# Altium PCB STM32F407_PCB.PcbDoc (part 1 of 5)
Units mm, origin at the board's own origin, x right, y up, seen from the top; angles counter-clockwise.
Board outline 100.27 x 100.27 mm, 2 copper layers (Top Layer, Bottom Layer); 134 components, 132 nets, 659 pads, 288 vias.
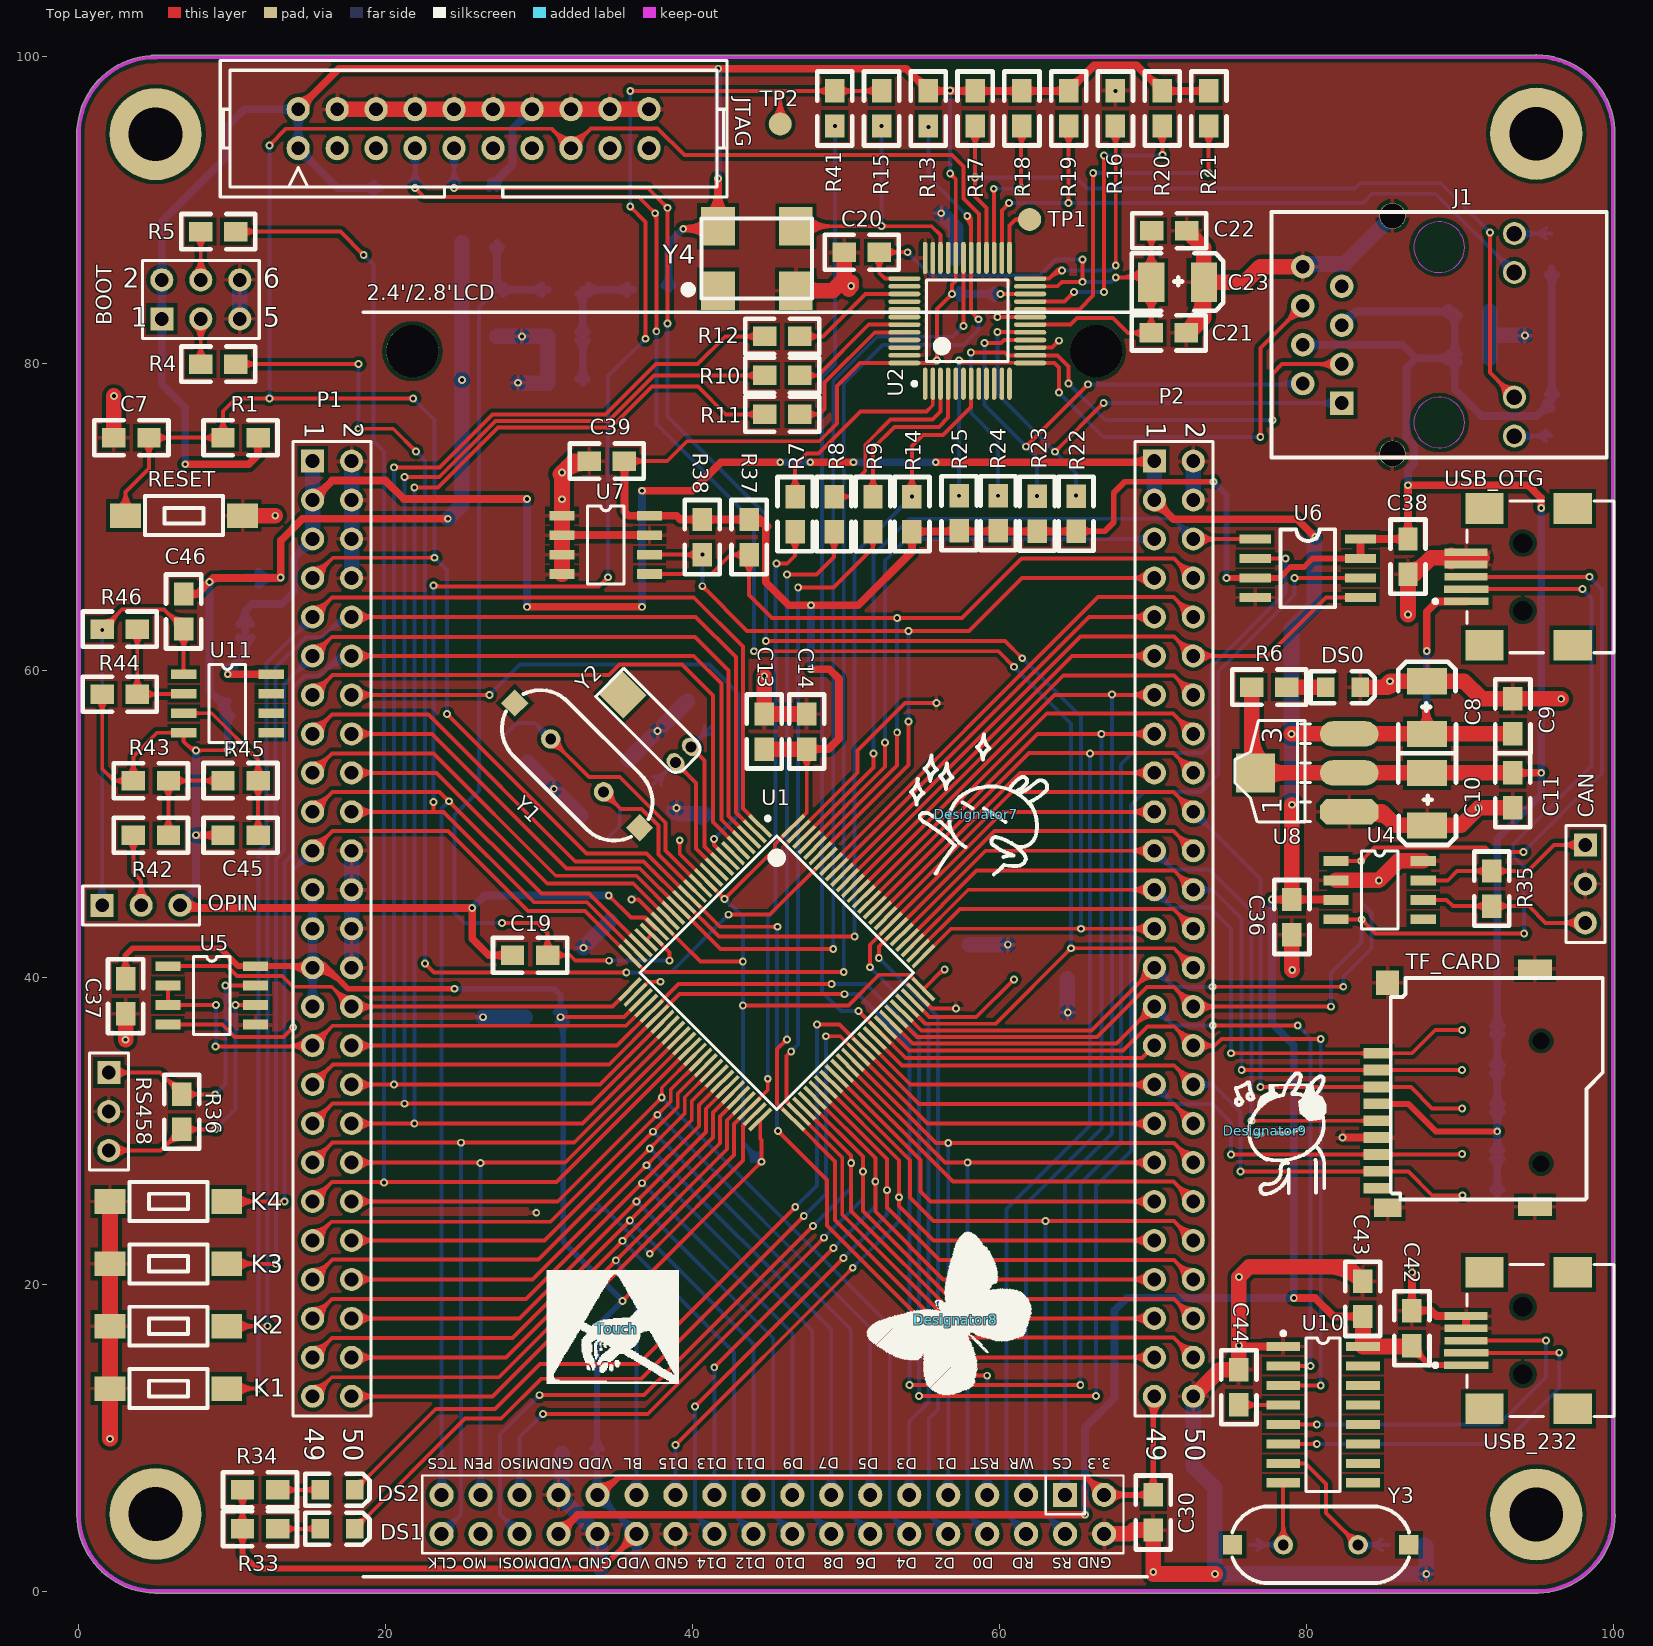
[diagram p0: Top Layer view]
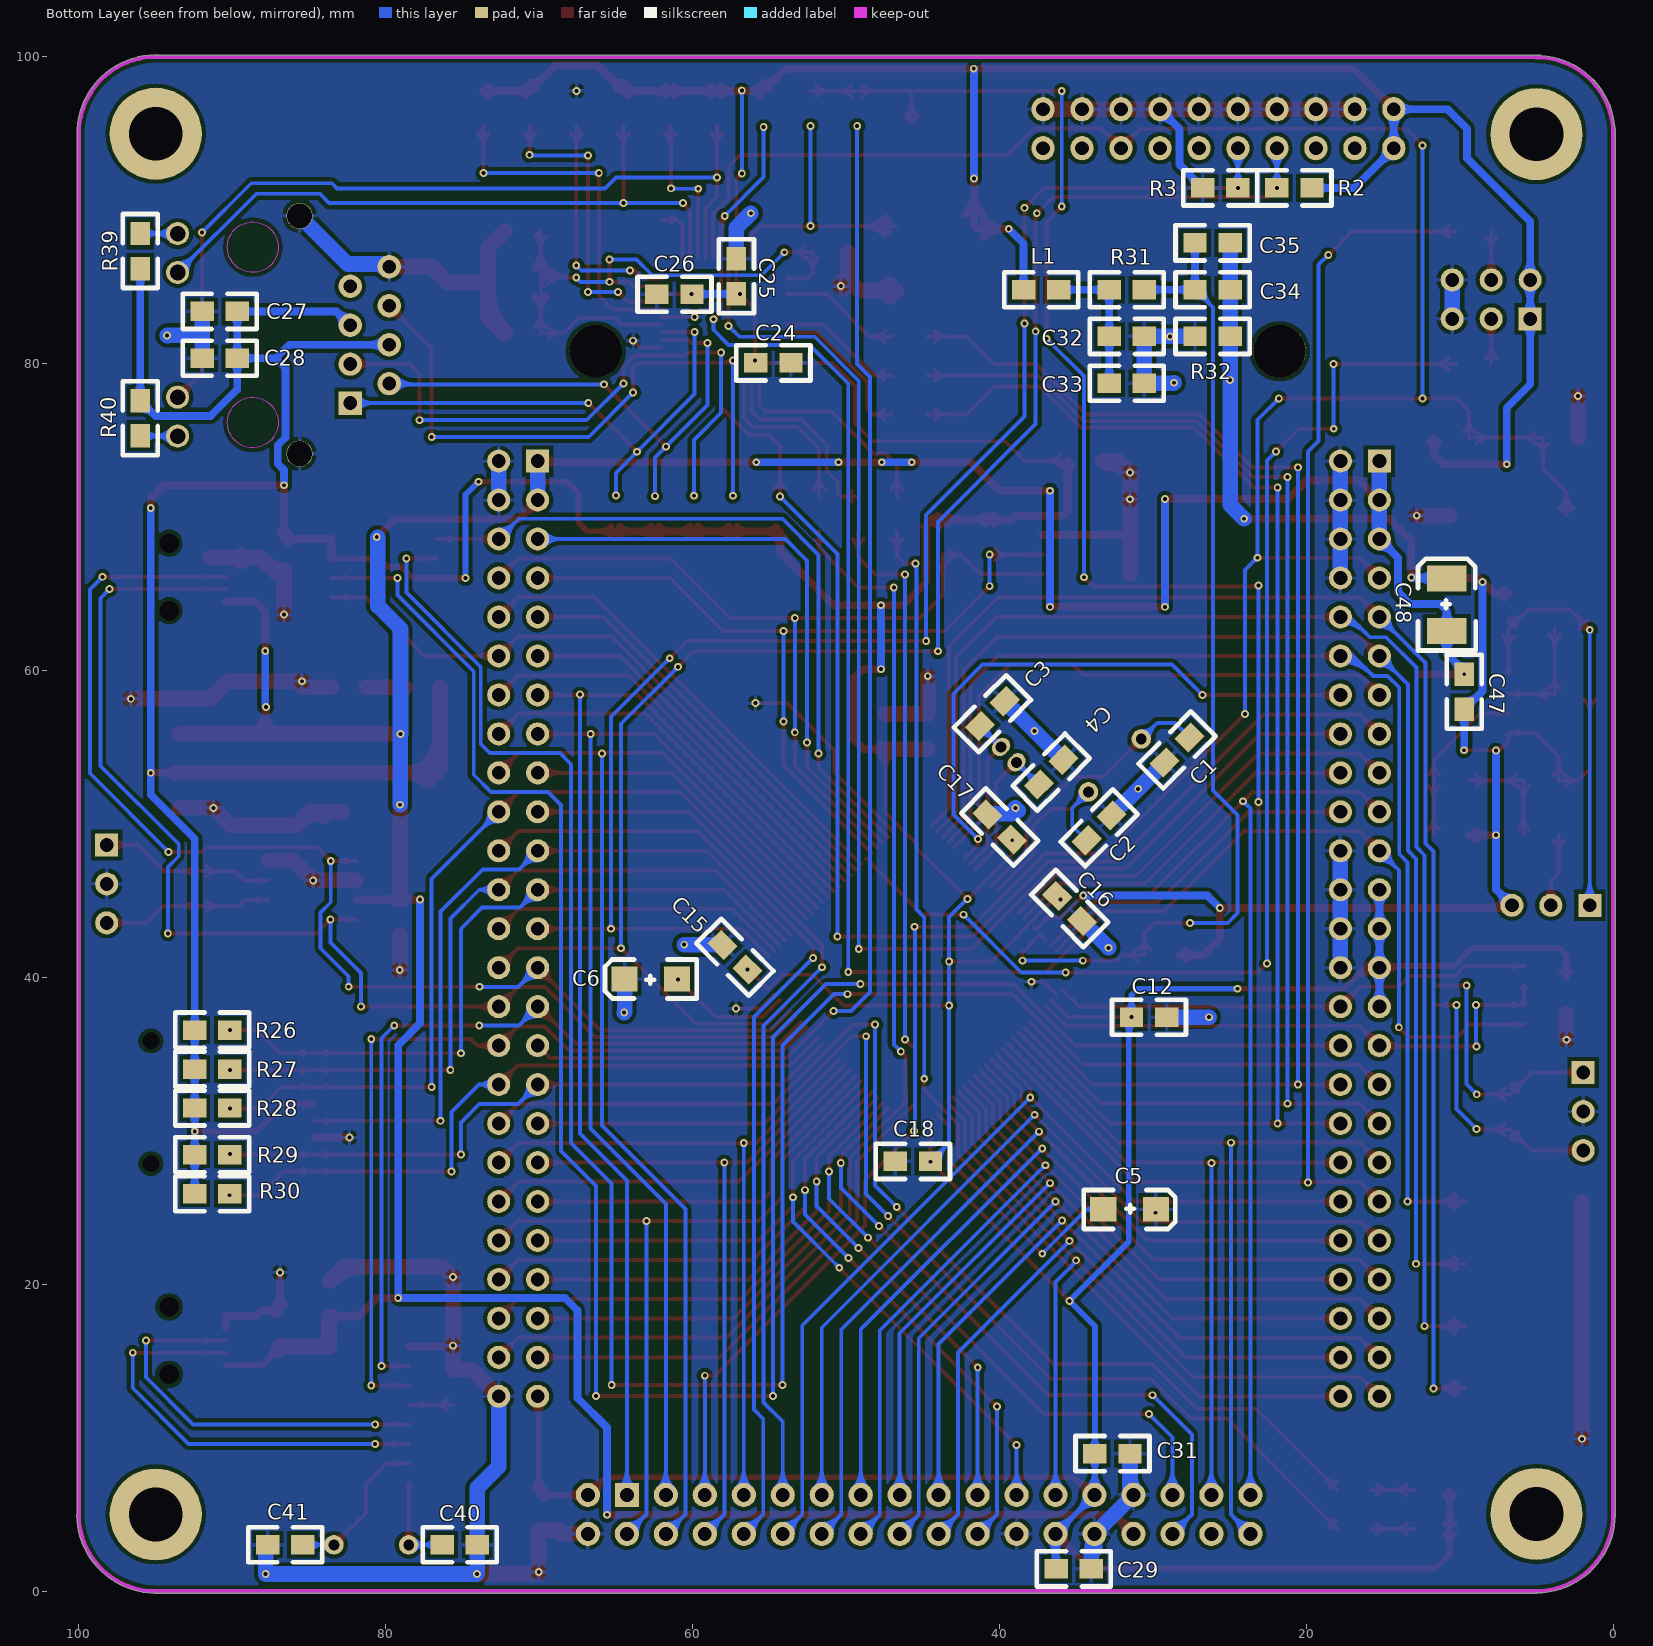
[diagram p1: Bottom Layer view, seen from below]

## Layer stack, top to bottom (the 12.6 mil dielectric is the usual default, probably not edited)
Top Layer: signal copper 0.0356
Dielectric: dielectric 0.32, FR-4, Dk 4.8
Bottom Layer: signal copper 0.0356

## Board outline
-0.127,4.992 cw(c0,4.994) -0.127,4.994 -0.127,4.996 cw(c5.011,5.025) -0.127,5.055 -0.127,95.199 cw(c0,95.199) -0.12,95.242 cw(c5.011,94.965) 4.716,100.095 cw(c4.801,100) 4.801,100.127 94.967,100.127 cw(c95.02,100.011) 95.02,100.139 cw(c94.989,95) 100.119,95.295 cw(c100,95.25) 100.127,95.25 100.127,95.029 cw(c94.989,95) 100.127,95 cw(c94.989,95) 100.127,94.971 cw(c94.989,95) 100.127,94.97 100.127,94.971 100.127,5.033 cw(c100.011,4.98) 100.139,4.98 cw(c100.011,4.98) 100.139,4.98 cw(c95,5.011) 95.115,-0.126 cw(c95.098,0) 95.098,-0.127 95.03,-0.127 cw(c95,5.011) 94.97,-0.127 4.994,-0.127 cw(c4.994,0) 4.936,-0.113 cw(c5.011,5.025)

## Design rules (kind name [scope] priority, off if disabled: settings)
Clearance Clearance_1 [(InPolygon)] p1: gap=0.254
Clearance [All] p2: gap=0.178
ComponentClearance [All] p1 off: gap=0.254 collisioncheckmode=3 verticalgap=0.254 showdistances=FALSE
FabricationTestpoint [(IsPad And (OnTopLayer Or OnBottomLayer))] p1: side=3 testpointundercomponent=TRUE minsize=1.016 maxsize=2.54 preferedsize=1.524 minholesize=0 maxholesize=1.016 preferedholesize=0.813 testpointgrid=0.025 allowsidetop=TRUE allowsidebottom=TRUE usegrid=TRUE gridtolerance=0
Height [All] p1: minheight=0 maxheight=1000 prefheight=12.7
HoleSize [All] p1: absolutevalues=TRUE maxlimit=6 minlimit=0.025 maxpercent=80.000 minpercent=20.000
HoleToHoleClearance [All] p1: gap=0.152 allowstackedmicrovias=TRUE
MinimumSolderMaskSliver [All] p1: minsoldermaskwidth=0
PolygonConnect [All] p1: connectstyle=Relief reliefconductorwidth=0.254 reliefentries=4 polygonreliefangle="90 Angle"
RoutingVias [All] p1: holewidth=0.254 width=0.508 viastyle="Through Hole" minholewidth=0.152 minwidth=0.305 maxholewidth=0.457 maxwidth=0.762
SilkToSilkClearance [All] p1: silktosilkclearance=0
SilkscreenOverComponentPads [All] p1: minsilkscreentomaskgap=0
SolderMaskExpansion [All] p1: expansion=0.102
Width [All] p1: maxlimit=1.016 minlimit=0.254 preferedwidth=0.254
20 further rules are at their usual default settings.

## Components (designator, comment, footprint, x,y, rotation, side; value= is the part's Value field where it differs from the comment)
2.4'/2.8'LCD "TFT_LCD" DB2*17 64.287,6.274 r180 top locked
BOOT "Header 3X2" HDR2X3 5.41,82.931 r0 top
C1 "20PF" 0805 29.235,54.026 r135 bottom
C2 "20PF" 0805 34.315,48.946 r135 bottom
C3 "20PF" 0805 41.275,56.388 r135 bottom
C4 "20PF" 0805 37.44,52.578 r135 bottom
C5 "1uF" 1206+ 33.238,24.881 r180 bottom
C6 "1uF" 1206+ 61.011,39.903 r0 bottom
C7 "104" 0805 4.572,75.184 r180 top
C8 "1uF" 1210+ 87.884,55.88 r90 top
C9 "104" 0805 93.472,55.88 r90 top
C10 "1uF" 1210+ 87.884,53.34 r270 top
C11 "104" 0805 93.472,53.34 r270 top
C12 "104" 0805 31.394,37.414 r180 bottom
C13 "104" 0805 44.679,57.175 r270 top
C14 "104" 0805 47.447,57.175 r270 top
C15 "104" 0805 56.439,40.513 r45 bottom
C16 "104" 0805 34.62,43.688 r45 bottom
C17 "104" 0805 40.792,50.622 r225 bottom
C18 "104" 0805 46.787,28.016 r180 bottom
C19 "104" 0805 30.556,41.453 r180 top
C20 "104" 0805 52.172,87.274 r180 top
C21 "104" 0805 69.901,82.017 r0 top
C22 "104" 0805 69.926,88.671 r0 top
C23 "10uf" 1210+（3528） 69.901,85.319 r0 top
C24 "104" 0805 55.88,80.061 r180 bottom
C25 "104" 0805 57.15,84.557 r90 bottom
C26 "104" 0805 60.046,84.531 r0 bottom
C27 "104" 0805 89.687,83.414 r0 bottom
C28 "104" 0805 89.687,80.366 r0 bottom
C29 "104" 0805 34.011,1.448 r0 bottom
C30 "104" 0805 70.028,3.988 r90 top
C31 "104" 0805 31.496,8.966 r0 bottom
C32 "105" 0805 32.842,81.788 r180 bottom
C33 "104" 0805 32.842,78.74 r180 bottom
C34 "105" 0805 27.254,84.836 r180 bottom
C35 "104" 0805 27.254,87.884 r180 bottom
C36 "104" 0805 79.07,42.799 r90 top
C37 "104" 0805 3.048,39.929 r270 top
C38 "104" 0805 86.639,68.58 r270 top
C39 "104" 0805 35.56,73.66 r180 top
C40 "20PF" 0805 76.327,3.023 r180 bottom
C41 "20PF" 0805 85.42,3.023 r0 bottom
C42 "104" 0805 86.893,18.288 r270 top
C43 "10uF" 0805 83.693,20.193 r270 top
C44 "104" 0805 75.616,12.141 r90 top
C45 "104" 0805 11.684,49.276 r180 top
C46 "104" 0805 6.833,64.999 r270 top
C47 "104" 0805 9.703,59.766 r270 bottom
C48 "10uF" 1210+（3528） 10.846,62.586 r90 bottom
CAN "Header 3" HDR1X3 98.196,48.641 r270 top
Designator7 "Comment" TJ0 58.496,50.648 r0 top
Designator8 "Comment" ST_BLY 57.15,17.678 r45 top
Designator9 "Comment" TJ3 77.343,29.997 r0 top
DS0 "LED" SMDLED 81.28,58.928 r0 top
DS1 "LED" SMDLED 15.748,4.064 r0 top
DS2 "LED" SMDLED 15.748,6.604 r0 top
J1 "RJ45" HR911105A 88.671,81.89 r270 top
JTAG "JTAG" JTAG_20 25.73,95.326 r0 top locked
K1 "KEY" SW 9.652,13.208 r180 top
K2 "KEY" SW 9.652,17.272 r180 top
K3 "KEY" SW 9.652,21.336 r180 top
K4 "KEY" SW 9.652,25.4 r180 top
L1 "Inductor" 0805 38.43,84.836 r180 bottom
OPIN "Header 3" HDR1X3 1.524,44.704 r0 top
P1 "Header 25X2" HDR2X25 15.24,73.66 r270 top
P2 "Header 25X2" HDR2X25 70.104,73.66 r270 top
R1 "10K" 0805 11.684,75.184 r180 top
R2 "10K" 0805 19.634,91.465 r0 bottom
R3 "10K" 0805 24.46,91.465 r0 bottom
R4 "100K" 0805 7.95,79.985 r0 top
R5 "100K" 0805 7.95,88.621 r0 top
R6 "510" 0805 78.74,58.928 r180 top
R7 "33" 0805 46.684,69.063 r90 top
R8 "33" 0805 49.224,69.063 r90 top
R9 "33" 0805 51.764,69.063 r90 top
R10 "33" 0805 44.704,79.248 r0 top
R11 "33" 0805 44.704,76.708 r0 top
R12 "33" 0805 44.704,81.788 r0 top
R13 "10k" 0805 55.372,95.504 r90 top
R14 "10k" 0805 54.304,69.063 r90 top
R15 "0" 0805 52.324,95.504 r90 top
R16 "4.87k" 0805 67.566,97.79 r270 top
R17 "10K" 0805 58.42,95.504 r90 top
R18 "10K" 0805 61.468,95.504 r90 top
R19 "10K" 0805 64.516,95.504 r90 top
R20 "2.2k" 0805 70.614,97.79 r270 top
R21 "2.2k" 0805 73.662,97.79 r270 top
R22 "47" 0805 64.999,69.088 r90 top
R23 "47" 0805 62.459,69.088 r90 top
R24 "47" 0805 59.917,69.113 r90 top
R25 "47" 0805 57.377,69.113 r90 top
R26 "10K" 0805 92.456,36.576 r180 bottom
R27 "10K" 0805 92.456,34.036 r180 bottom
R28 "10K" 0805 92.456,31.496 r180 bottom
R29 "10K" 0805 92.456,28.448 r180 bottom
R30 "10K" 0805 92.456,25.908 r180 bottom
R31 "47" 0805 32.842,84.836 r180 bottom
R32 "0" 0805 27.254,81.788 r180 bottom
R33 "510" 0805 10.668,4.064 r0 top
R34 "510" 0805 10.668,6.604 r0 top
R35 "120" 0805 92.1,46.939 r270 top
R36 "120" 0805 6.706,32.385 r270 top
R37 "10K" 0805 43.688,67.564 r90 top
R38 "10K" 0805 40.64,67.564 r90 top
R39 "240" 0805 96.012,86.208 r90 bottom
R40 "240" 0805 96.012,75.311 r90 bottom
R41 "0" 0805 49.276,95.504 r90 top
R42 "10K" 0805 3.556,49.276 r0 top
R43 "1K" 0805 3.556,52.832 r0 top
R44 "10K" 0805 1.524,58.471 r0 top
R45 "1K" 0805 11.684,52.832 r180 top
R46 "0" 0805 1.524,62.713 r0 top
RESET "KEY" SW 3.048,70.104 r0 top
RS458 "Header 3" HDR1X3 1.956,33.807 r270 top
TF_CARD "TF_CARD" TF 84.633,26.264 r90 top
Touch "Touch" THAND 35.077,17.12 r0 top
TP1 "TEST POINT" TP-1.5 61.976,89.408 r0 top
TP2 "TEST POINT" TP-1.5 45.72,95.631 r90 top
U1 "STM32F407VET6" LQFP100 45.491,40.31 r315 top locked
U2 "DP83848" LQFP48 57.912,82.804 r90 top locked
U4 "TJA1050" SOP-8 81.94,47.6 r0 top
U5 "SP3485" SOP-8 5.817,40.742 r0 top
U6 "W25Q64" SOIC-8 76.683,68.58 r0 top
U7 "24C02" SOP-8 31.496,70.104 r0 top
U8 "AMS1117-3.3" AMS1117 82.804,50.8 r90 top
U10 "CH340G" SOP16M 81.102,11.506 r270 top
U11 "LM358" SOP-8 6.833,59.766 r0 top
USB_232 "USB" USB/SM0.8-6H5 90.424,14.732 r0 top
USB_OTG "USB" USB/SM0.8-6H5 90.424,64.516 r0 top
Y1 "8MHz" XTAL_US 30.759,55.55 r315 top
Y2 "32.768KHz" XTAL32 38.887,54.026 r135 top
Y3 "12MHz" XTAL_US 83.388,3.023 r180 top
Y4 "XTAL_50MHz" OSC-7050 44.196,86.868 r0 top

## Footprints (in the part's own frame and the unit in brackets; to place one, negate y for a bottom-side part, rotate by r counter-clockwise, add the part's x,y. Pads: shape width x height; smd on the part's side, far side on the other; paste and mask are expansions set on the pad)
0805 [mil]
  rect 60x50 smd: 1(0,-0.07) 2(90,-0.06)
  silkscreen extent -50,-45 140,45
1206+ [mm] "1206 封装有极性,1脚正,稳压管7.5V9.1V12V"
  rect 1.7x1.6 smd: 1(0,0) 2(3.429,0)
  silkscreen extent -1.27,-1.27 4.7,1.27
1210+ [mm] "1210 封装有极性,1脚正,稳压管7.5V9.1V12V"
  rect 1.7x2.6 smd: 1(0,0) 2(3.429,0)
  silkscreen extent -1.27,-1.88 4.7,1.88
1210+（3528） [mm] "1210 封装有极性,1脚正,稳压管7.5V9.1V12V"
  rect 1.7x2.6 smd: 1(0,0) 2(3.429,0)
  silkscreen extent -1.27,-1.88 4.7,1.88
AMS1117 [mil]
  oct 65x150 smd: 1(0.03,-0.06)
  oval 65x150 smd: 2(100.03,-0.06) 3(200.03,-0.06)
  rect 100x100 smd: 4(100.03,239.94)
  silkscreen extent -26,100 234,293
DB2*17 [mil]
  rect 62x62 hole 35.43: 1(0,0)
  round 62 hole 35.43: 2(0,100) 3(100,0) 4(100,100) 5(200,0) 6(200,100) 7(300,0) 8(300,100) 9(400,0) 10(400,100) 11(500,0) 12(500,100) 13(600,0) 14(600,100) 15(700,0) 16(700,100) 17(800,0) 18(800,100) 19(900,0) 20(900,100) 21(1000,0) 22(1000,100) 23(1100,0) 24(1100,100) 25(1200,0) 26(1200,100) 27(1300,0) 28(1300,100) 29(1400,0) 30(1400,100) 31(1500,0) 32(1500,100) 33(1600,0) 34(1600,100) 35(-100,0) 36(-100,100)
  round 133.86 hole 133.86: ""(-80,-2935) ""(1675,-2935)
  silkscreen extent -210,-3035 1800,210
HDR1X3 [mm] "Connector; Header; 3 Position"
  rect 1.5x1.5 hole 0.9: 1(0,0)
  round 1.5 hole 0.9: 2(2.54,0) 3(5.08,0)
  silkscreen extent -1.27,-1.27 6.35,1.27
HDR2X3 [mm] "Connector; Header; 3x2 Position"
  rect 1.5x1.5 hole 0.9: 1(0,0)
  round 1.5 hole 0.9: 2(0,2.54) 3(2.54,0) 4(2.54,2.54) 5(5.08,0) 6(5.08,2.54)
  silkscreen extent -1.27,-1.27 6.35,3.81
HDR2X25 [mm] "Connector; Header; 25x2 Position"
  rect 1.5x1.5 hole 0.9: 1(0,0)
  round 1.5 hole 0.9: 2(0,2.54) 3(2.54,0) 4(2.54,2.54) 5(5.08,0) 6(5.08,2.54) 7(7.62,0) 8(7.62,2.54) 9(10.16,0) 10(10.16,2.54) 11(12.7,0) 12(12.7,2.54) 13(15.24,0) 14(15.24,2.54) 15(17.78,0) 16(17.78,2.54) 17(20.32,0) 18(20.32,2.54) 19(22.86,0) 20(22.86,2.54) 21(25.4,0) 22(25.4,2.54) 23(27.94,0) 24(27.94,2.54) 25(30.48,0) 26(30.48,2.54) 27(33.02,0) 28(33.02,2.54) 29(35.56,0) 30(35.56,2.54) 31(38.1,0) 32(38.1,2.54) 33(40.64,0) 34(40.64,2.54) 35(43.18,0) 36(43.18,2.54) 37(45.72,0) 38(45.72,2.54) 39(48.26,0) 40(48.26,2.54) 41(50.8,0) 42(50.8,2.54) 43(53.34,0) 44(53.34,2.54) 45(55.88,0) 46(55.88,2.54) 47(58.42,0) 48(58.42,2.54) 49(60.96,0) 50(60.96,2.54)
  silkscreen extent -1.27,-1.27 62.23,3.81
HR911105A [mm]
  rect 1.524x1.524 hole 0.9: 1(4.45,-6.35)
  round 1.524 hole 0.9: 2(3.18,-8.89) 3(1.91,-6.35) 4(0.64,-8.89) 5(-0.63,-6.35) 6(-1.9,-8.89) 7(-3.17,-6.35) 8(-4.44,-8.89)
  round 1.5 hole 1.02: 9(6.6,4.9) 10(4.064,4.9) 11(-4.064,4.9) 12(-6.6,4.9)
  round 1.7 hole 1.65: 13(7.75,-3.048) 14(-7.75,-3.048)
  Keep-Out Layer circle w0.051: c5.716,0 r1.65
  Keep-Out Layer circle w0.051: c-5.714,0 r1.65
  silkscreen extent -8,-10.92 8,10.92
JTAG_20 [mm]
  oval 1.5x1.575 hole 0.9: 1(-11.43,-1.27) 2(-11.43,1.27) 3(-8.89,-1.27) 4(-8.89,1.27) 5(-6.35,-1.27) 6(-6.35,1.27) 7(-3.81,-1.27) 8(-3.81,1.27) 9(-1.27,-1.27) 10(-1.27,1.27) 11(1.27,-1.27) 12(1.27,1.27) 13(3.81,-1.27) 14(3.81,1.27) 15(6.35,-1.27) 16(6.35,1.27) 17(8.89,-1.27) 18(8.89,1.27) 19(11.43,-1.27) 20(11.43,1.27)
  silkscreen extent -16.51,-4.45 16.51,4.44
LQFP48 [mm] "Thin QFP, 48-Leads, Body 7x7mm, Pitch 0.5mm, IPC Low Density"
  oval 2.1x0.3 smd: 1(-4.1,2.75) 2(-4.1,2.25) 3(-4.1,1.75) 4(-4.1,1.25) 5(-4.1,0.75) 6(-4.1,0.25) 7(-4.1,-0.25) 8(-4.1,-0.75) 9(-4.1,-1.25) 10(-4.1,-1.75) 11(-4.1,-2.25) 12(-4.1,-2.75) 25(4.1,-2.75) 26(4.1,-2.25) 27(4.1,-1.75) 28(4.1,-1.25) 29(4.1,-0.75) 30(4.1,-0.25) 31(4.1,0.25) 32(4.1,0.75) 33(4.1,1.25) 34(4.1,1.75) 35(4.1,2.25) 36(4.1,2.75)
  oval 0.3x2.1 smd: 13(-2.75,-4.1) 14(-2.25,-4.1) 15(-1.75,-4.1) 16(-1.25,-4.1) 17(-0.75,-4.1) 18(-0.25,-4.1) 19(0.25,-4.1) 20(0.75,-4.1) 21(1.25,-4.1) 22(1.75,-4.1) 23(2.25,-4.1) 24(2.75,-4.1) 37(2.75,4.1) 38(2.25,4.1) 39(1.75,4.1) 40(1.25,4.1) 41(0.75,4.1) 42(0.25,4.1) 43(-0.25,4.1) 44(-0.75,4.1) 45(-1.25,4.1) 46(-1.75,4.1) 47(-2.25,4.1) 48(-2.75,4.1)
  silkscreen extent -4.22,-2.65 2.65,3.57
LQFP100 [mm] "TSQFP, 100-Leads, Body 16.0x16.0mm (max), Pitch 0.50mm, IPC Medium Density"
  rect 2x0.254 smd: 1(-7.525,6) 2(-7.525,5.5) 3(-7.525,5) 4(-7.525,4.5) 5(-7.525,4) 6(-7.525,3.5) 7(-7.525,3) 8(-7.525,2.5) 9(-7.525,2) 10(-7.525,1.5) 11(-7.525,1) 12(-7.525,0.5) 13(-7.525,0) 14(-7.525,-0.5) 15(-7.525,-1) 16(-7.525,-1.5) 17(-7.525,-2) 18(-7.525,-2.5) 19(-7.525,-3) 20(-7.525,-3.5) 21(-7.525,-4) 22(-7.525,-4.5) 23(-7.525,-5) 24(-7.525,-5.5) 25(-7.525,-6) 51(7.525,-6) 52(7.525,-5.5) 53(7.525,-5) 54(7.525,-4.5) 55(7.525,-4) 56(7.525,-3.5) 57(7.525,-3) 58(7.525,-2.5) 59(7.525,-2) 60(7.525,-1.5) 61(7.525,-1) 62(7.525,-0.5) 63(7.525,0) 64(7.525,0.5) 65(7.525,1) 66(7.525,1.5) 67(7.525,2) 68(7.525,2.5) 69(7.525,3) 70(7.525,3.5) 71(7.525,4) 72(7.525,4.5) 73(7.525,5) 74(7.525,5.5) 75(7.525,6)
  rect 0.254x2 smd: 26(-6,-7.525) 27(-5.5,-7.525) 28(-5,-7.525) 29(-4.5,-7.525) 30(-4,-7.525) 31(-3.5,-7.525) 32(-3,-7.525) 33(-2.5,-7.525) 34(-2,-7.525) 35(-1.5,-7.525) 36(-1,-7.525) 37(-0.5,-7.525) 38(0,-7.525) 39(0.5,-7.525) 40(1,-7.525) 41(1.5,-7.525) 42(2,-7.525) 43(2.5,-7.525) 44(3,-7.525) 45(3.5,-7.525) 46(4,-7.525) 47(4.5,-7.525) 48(5,-7.525) 49(5.5,-7.525) 50(6,-7.525) 76(6,7.525) 77(5.5,7.525) 78(5,7.525) 79(4.5,7.525) 80(4,7.525) 81(3.5,7.525) 82(3,7.525) 83(2.5,7.525) 84(2,7.525) 85(1.5,7.525) 86(1,7.525) 87(0.5,7.525) 88(0,7.525) 89(-0.5,7.525) 90(-1,7.525) 91(-1.5,7.525) 92(-2,7.525) 93(-2.5,7.525) 94(-3,7.525) 95(-3.5,7.525) 96(-4,7.525) 97(-4.5,7.525) 98(-5,7.525) 99(-5.5,7.525) 100(-6,7.525)
  silkscreen extent -7.65,-6.3 6.3,6.82
OSC-7050 [mm]
  rect 2.2x2.5 smd: 1(-2.54,-2.1) 2(2.54,-2.1) 3(2.54,2.1) 4(-2.54,2.1)
  silkscreen extent -4.72,-2.6 3.6,2.6
SMDLED [mil]
  rect 45x50 smd: 1(0,0) 2(88,0)
  silkscreen extent -39,-41 126,41
SOIC-8 [mil]
  rect 80x24 smd: 1(0,0) 2(0,-50.06) 3(0,-100.06) 4(0,-150.06) 5(270,-150) 6(270,-100) 7(270,-50) 8(270,0)
  silkscreen extent 65,-175 205,25
SOP16M [mm]
  rect 0.6x2.2 smd: 1(-4.445,-2.6) 2(-3.175,-2.6) 3(-1.905,-2.6) 4(-0.635,-2.6) 5(0.635,-2.6) 6(1.905,-2.6) 7(3.175,-2.6) 8(4.445,-2.6) 9(4.445,2.6) 10(3.175,2.6) 11(1.905,2.6) 12(0.635,2.6) 13(-0.635,2.6) 14(-1.905,2.6) 15(-3.175,2.6) 16(-4.445,2.6)
  silkscreen extent -5.42,-2.72 5,1.1
SOP-8 [mil]
  rect 65x25 smd: 1(0,0) 2(0,-50) 3(0,-100) 4(0,-150) 5(224.41,-150) 6(224.41,-100) 7(224.41,-50) 8(224.41,0)
  silkscreen extent 65,-175 159,25
ST_BLY [mm]
  silkscreen extent -4.85,-3.81 4.85,3.61
SW [mm]
  rect 2x1.6 smd: 1(0,0) 2(7.62,0)
  silkscreen extent 1.27,-1.27 6.35,1.27
TF [mm]
  round 1 hole 1.1 unplated: 0(1.6,-10.678) 0(9.6,-10.678)
  rect 0.7x1.8 smd: 1(8.8,0) 2(7.7,0) 3(6.6,0) 4(5.5,0) 5(4.4,0) 6(3.3,0) 7(2.2,0) 8(1.1,0) 9(0,0)
  rect 1.2x1.8 smd: 10(-1.27,-0.686)
  rect 1.2x2.2 smd: 11(-1.2,-10.278) 13(14.3,-10.278)
  rect 1.6x1.5 smd: 12(13.4,-0.678)
  silkscreen extent -0.74,-14.7 13.7,-0.88
THAND [mm]
  silkscreen extent -4.57,-3.56 4.01,3.81
TJ0 [mm] "TSJ"
  silkscreen extent -4.27,-3.94 4.62,5.21
TJ3 [mm] "TSJ"
  silkscreen extent -1.93,-4.12 3.98,3.76
TP-1.5 [mm]
  round 1.5 smd: 1(0,0)
USB/SM0.8-6H5 [mm]
  rect 2.9x0.5 smd: 1(0,0) 2(0,0.8)
  rect 2.8x0.5 smd: 3(0,1.6) 4(0,2.4) 5(0,3.2)
  rect 2.5x2 smd: 6(1.2,6.05) 7(6.954,6.05) 8(1.2,-2.85) 9(6.954,-2.85)
  round 0.6 hole 1.27 unplated: MH1(3.7,3.8) MH2(3.7,-0.6)
  silkscreen extent -2.12,-3.35 9.65,6.55
XTAL32 [mil]
  oval 50x40 hole 28: 1(0,0) 2(0,-56)
  rect 92.13x86 smd: ""(220,-27)
  silkscreen extent -28,-77 264,25
XTAL_US [mm]
  round 1.27 hole 0.711: 1(0,0) 2(4.88,0)
  rect 1.27x1.27 smd: ""(-3.31,0) ""(8.19,0)
  silkscreen extent -3.33,-2.5 8.21,2.5

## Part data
BOOT: "Header, 3-Pin, Dual row"
C1 C2 C3 C4 C7 C9 C11 C12 C13 C14 C15 C16 C17 C18 C19 C20 C21 C22 C24 C25 C26 C27 C28 C29 C30 C31 C32 C33 C34 C35 C36 C37 C38 C39 C40 C41 C42 C43 C44 C45 C46 C47: library part C
C5 C6 C8 C10 C23 C48: library part "CAP POL"
CAN OPIN RS458: "Header, 3-Pin"
DS0 DS1 DS2: "Typical RED, GREEN, YELLOW, AMBER GaAs LED"
J1: library part HR911105
K1 K2 K3 K4 RESET: library part KEY_M
P1 P2: "Header, 25-Pin, Dual row"
R1 R2 R3 R4 R5 R6 R7 R8 R9 R10 R11 R12 R13 R14 R15 R16 R17 R18 R19 R20 R21 R22 R23 R24 R25 R26 R27 R28 R29 R30 R31 R32 R33 R34 R35 R36 R37 R38 R39 R40 R41 R42 R43 R44 R45 R46: library part R
TP1 TP2: library part TEST-POINT
U5: library part MAX3485
U6: library part W25X16, "W25X16;SST25VF016;MX25L1605"
U8: library part AMS1117
U10: "USB2UART"
Y1 Y2 Y3: library part XTAL, "Crystal Oscillator"

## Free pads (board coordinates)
  round 6 hole 3.5: 1(5.004,94.971) 2(94.996,94.996) 3(94.996,5.004) 4(5.004,5.029)

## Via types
v1: diameter 0.508, hole 0.254, Top Layer to Bottom Layer, 288 vias

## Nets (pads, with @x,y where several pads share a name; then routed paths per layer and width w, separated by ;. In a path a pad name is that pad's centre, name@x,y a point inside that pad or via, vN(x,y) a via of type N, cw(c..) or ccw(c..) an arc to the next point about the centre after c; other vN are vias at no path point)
3V3: 2.4'/2.8'LCD.24 2.4'/2.8'LCD.25 2.4'/2.8'LCD.35 BOOT.1 BOOT.2 C10.1 C11.1 C12.1 C13.2 C14.2 C15.1 C16.2 C17.2 C18.2 C24.1 C25.1 C26.1 C27.1 C28.1 C29.2 C30.2 C31.2 C37.1 C38.1 C39.1 J1.4 J1.5 JTAG.1 JTAG.2 L1.1 P1.23 P1.25 P1.27 P1.29 P2.49 R1.1 R2.1 R6.2 R13.2 R14.1 R17.2 R18.2 R19.2 R20.1 R21.1 R22.1 R23.1 R24.1 R25.1 R26.1 R27.1 R28.1 R29.1 R30.1 R33.1 R34.1 R37.2 R38.2 R39.1 R40.2 TF_CARD.4 U1.11 U1.19 U1.28 U1.50 U1.75 U1.100 U2.22 U2.32 U2.48 U5.8 U6.3 U6.7 U6.8 U7.8 U8.2 U8.4 Y4.4 | length 1014.7
  Top Layer w0.254: v1(31.394,37.414) 35.525,37.414 U1.28@36.635,38.524 ; v1(35.433,18.923) v1(44.501,27.991) 44.501,29.413 44.413,29.501 U1.50@44.413,30.746 ; C39.1@35.56,73.662 38.356,73.662 39.649,74.955 48.26,74.955 49.428,76.124 49.428,78.562 50.92,80.054 U2.48@53.812,80.054 53.817,80.059 55.776,80.059 v1(55.931,80.213) 55.931,83.566 v1(56.921,84.557) 56.921,85.166 57.162,85.407 U2.32@57.162,86.904 57.162,92.038 v1(56.794,92.405) ; v1(36.017,45.087) 36.471,45.087 U1.19@38.049,43.509 39.268,42.291 ; v1(39.167,48.946) 39.167,48.049 U1.11@40.878,46.338 ; 39.268,42.291 40.512,41.046 v1(43.282,41.046) ; U1.11@40.878,46.321 v1(42.088,45.11) 45.364,48.387 45.364,48.668 U1.100@46.57,49.873 47.446,50.749 C14.2@47.446,54.889 ; v1(43.282,38.176) 50.165,38.176 52.172,40.183 54.104,40.183 U1.75@55.055,39.231 56.338,40.514 v1(56.438,40.514) ; v1(60.071,84.557) 60.074,84.554 U2.22@62.012,84.554 ; 31.701,37.414 cw(c31.701,37.721) 31.484,37.504 ccw(c31.701,37.721) 31.701,37.414 ; 31.701,37.414 ccw(c31.701,37.108) 31.484,37.324 cw(c31.701,37.108) 31.701,37.414 ; 35.65,19.14 cw(c35.433,19.357) 35.433,19.05 ccw(c35.433,19.357) 35.65,19.14 ; 35.65,19.14 ccw(c35.867,18.923) 35.56,18.923 cw(c35.867,18.923) 35.65,19.14 ; 36.324,45.087 cw(c36.324,45.394) 36.107,45.177 ccw(c36.324,45.394) 36.324,45.087 ; 36.324,45.087 ccw(c36.324,44.781) 36.107,44.997 cw(c36.324,44.781) 36.324,45.087 ; 36.913,73.662 cw(c36.913,74.888) 36.046,74.021 ccw(c36.913,74.888) 36.913,73.662 ; 36.913,73.662 ccw(c36.913,72.435) 36.046,73.302 cw(c36.913,72.435) 36.913,73.662 ; 39.167,48.639 cw(c39.473,48.639) 39.257,48.856 ccw(c39.473,48.639) 39.167,48.639 ; 39.167,48.639 ccw(c38.86,48.639) 39.077,48.856 cw(c38.86,48.639) 39.167,48.639 ; 41.871,45.327 cw(c41.654,45.11) 41.961,45.11 ccw(c41.654,45.11) 41.871,45.327 ; 41.871,45.327 ccw(c42.088,45.544) v1@42.088,45.237 ; 41.871,45.327 ccw(c42.088,45.544) v1@42.088,45.237 ; v1@42.088,45.237 ccw(c42.088,45.544) 42.305,45.327 ; v1@42.088,45.237 ccw(c42.088,45.544) 42.305,45.327 ; 42.305,45.327 ccw(c42.521,45.11) 42.215,45.11 cw(c42.521,45.11) 42.305,45.327 ; 42.975,41.046 cw(c42.975,40.74) 43.192,40.957 ccw(c42.975,40.74) 42.975,41.046 ; 42.975,41.046 ccw(c42.975,41.353) 43.192,41.136 cw(c42.975,41.353) 42.975,41.046 ; 43.588,38.176 cw(c43.588,38.483) 43.371,38.266 ccw(c43.588,38.483) 43.588,38.176 ; 43.588,38.176 ccw(c43.588,37.87) 43.371,38.086 cw(c43.588,37.87) 43.588,38.176 ; 44.284,27.774 cw(c44.501,27.557) 44.501,27.864 ccw(c44.501,27.557) 44.284,27.774 ; 44.284,27.774 ccw(c44.067,27.991) 44.374,27.991 cw(c44.067,27.991) 44.284,27.774 ; 44.501,28.297 cw(c44.194,28.297) 44.411,28.081 ccw(c44.194,28.297) 44.501,28.297 ; 44.501,28.297 ccw(c44.807,28.297) 44.591,28.081 cw(c44.807,28.297) 44.501,28.297 ; 47.446,53.536 cw(c48.672,53.536) 47.805,54.403 ccw(c48.672,53.536) 47.446,53.536 ; 47.446,53.536 ccw(c46.219,53.536) 47.086,54.403 cw(c46.219,53.536) 47.446,53.536 ; v1@55.841,80.303 ccw(c55.624,80.52) 55.931,80.52 ; v1@55.841,80.303 cw(c55.251,80.893) 55.251,80.059 ccw(c55.251,80.893) v1@55.841,80.303 ; v1@55.841,80.303 ccw(c55.624,80.52) 55.931,80.52 ; 55.931,80.52 ccw(c56.237,80.52) 56.021,80.303 cw(c56.237,80.52) 55.931,80.52 ; 56.705,84.34 cw(c56.921,84.123) 56.921,84.43 ccw(c56.921,84.123) 56.705,84.34 ; 56.705,84.34 ccw(c56.488,84.557) 56.794,84.557 cw(c56.488,84.557) 56.705,84.34 ; 56.921,84.863 cw(c56.615,84.863) 56.832,84.646 ccw(c56.615,84.863) 56.921,84.863 ; 56.921,84.863 ccw(c57.228,84.863) 57.011,84.646 cw(c57.228,84.863) 56.921,84.863 ; 57.011,92.188 cw(c57.228,92.405) 56.921,92.405 ccw(c57.228,92.405) 57.011,92.188 ; 57.011,92.188 ccw(c56.794,91.972) 56.794,92.278 cw(c56.794,91.972) 57.011,92.188 ; 56.05,40.227 cw(c56.438,39.839) 56.438,40.387 ccw(c56.438,39.839) 56.05,40.227 ; v1@60.161,84.467 cw(c60.371,84.256) 60.371,84.554 ccw(c60.371,84.256) v1@60.161,84.467 ; v1@60.161,84.646 ccw(c60.384,84.869) 60.384,84.554 cw(c60.384,84.869) v1@60.161,84.646
  Top Layer w0.381: C37.1@3.046,39.929 3.046,41.451 3.505,41.91 9.22,41.91 10.389,40.742 U5.8@11.517,40.742 15.138,40.742 P1.27@15.24,40.64 16.18,40.64 ; R34.1@10.668,6.602 R33.1@10.668,4.062 10.668,2.413 11.608,1.473 34.087,1.473 2.4'/2.8'LCD.24@36.347,3.734 ; v1(24.486,39.268) 17.551,39.268 16.18,40.64 ; 2.4'/2.8'LCD.25@33.807,6.274 34.036,6.274 35.192,7.429 ; R22.1@65,69.088 66.878,69.088 67.462,69.672 67.462,71.603 68.174,72.314 v1(73.965,72.314) ; P2.49@70.029,12.625 C30.2@70.029,6.274 2.4'/2.8'LCD.35@66.827,6.274 65.672,7.429 35.192,7.429 ; v1(74.805,66.038) U6.3@76.683,66.038 78.272,66.038 78.985,66.751 79.858,66.751 80.416,67.31 U6.7@83.541,67.31 ; TF_CARD.4@84.633,31.764 86.651,31.764 88.443,29.972 v1(92.456,29.972) ; 3.046,41.129 cw(c1.973,41.129) 2.732,40.37 ccw(c1.973,41.129) 3.046,41.129 ; 3.046,41.129 ccw(c4.119,41.129) 3.361,40.37 cw(c4.119,41.129) 3.046,41.129 ; 10.668,2.989 cw(c11.741,2.989) 10.982,3.748 ccw(c11.741,2.989) 10.668,2.989 ; 10.668,2.989 ccw(c9.595,2.989) 10.354,3.748 cw(c9.595,2.989) 10.668,2.989 ; 10.668,5.135 cw(c9.595,5.135) 10.354,4.377 ccw(c9.595,5.135) 10.668,5.135 ; 10.668,5.135 ccw(c11.741,5.135) 10.982,4.377 cw(c11.741,5.135) 10.668,5.135 ; 10.668,5.529 cw(c11.741,5.529) 10.982,6.288 ccw(c11.741,5.529) 10.668,5.529 ; 10.668,5.529 ccw(c9.595,5.529) 10.354,6.288 cw(c9.595,5.529) 10.668,5.529 ; 16.18,40.64 cw(c16.18,41.149) 15.732,40.907 ccw(c16.18,41.149) 16.18,40.64 ; 16.18,40.64 ccw(c16.18,40.131) 15.732,40.373 cw(c16.18,40.131) 16.18,40.64 ; 35.192,7.429 cw(c33.842,8.779) 33.816,6.871 ccw(c33.842,8.779) 35.192,7.429 ; 35.328,2.715 cw(c36.347,1.696) 36.347,3.137 ccw(c36.347,1.696) 35.328,2.715 ; 35.328,2.715 ccw(c34.309,3.734) 35.75,3.734 cw(c34.309,3.734) 35.328,2.715 ; 65.808,7.293 cw(c64.789,6.274) 66.23,6.274 ccw(c64.789,6.274) 65.808,7.293 ; 65.808,7.293 ccw(c66.827,8.312) 66.827,6.871 cw(c66.827,8.312) 65.808,7.293 ; 66.073,69.088 cw(c66.073,70.161) 65.315,69.402 ccw(c66.073,70.161) 66.073,69.088 ; 66.073,69.088 ccw(c66.073,68.015) 65.315,68.774 cw(c66.073,68.015) 66.073,69.088 ; 68.268,6.274 cw(c68.268,7.715) 67.249,6.696 ccw(c68.268,7.715) 68.268,6.274 ; 68.268,6.274 ccw(c68.268,4.833) 67.249,5.852 cw(c68.268,4.833) 68.268,6.274 ; 68.956,6.274 cw(c68.956,5.201) 69.715,5.959 ccw(c68.956,5.201) 68.956,6.274 ; 68.956,6.274 ccw(c68.956,7.347) 69.715,6.588 cw(c68.956,7.347) 68.956,6.274 ; 70.029,7.474 cw(c68.956,7.474) 69.715,6.715 ccw(c68.956,7.474) 70.029,7.474 ; 70.029,7.474 ccw(c71.103,7.474) 70.344,6.715 cw(c71.103,7.474) 70.029,7.474 ; 85.568,31.764 cw(c85.568,32.149) 85.296,31.876 ccw(c85.568,32.149) 85.568,31.764 ; 85.568,31.764 ccw(c85.568,31.378) 85.296,31.651 cw(c85.568,31.378) 85.568,31.764 ; 13.644,40.742 cw(c13.644,39.044) 14.844,40.244 ccw(c13.644,39.044) 13.644,40.742 ; 14.135,40.742 ccw(c14.135,41.745) 14.844,41.036 cw(c14.135,41.745) 14.135,40.742 ; P1.27@15.109,40.794 cw(c15.566,40.256) 16.065,40.755 ccw(c15.566,40.256) P1.27@15.109,40.794 ; P1.27@15.24,40.462 cw(c15.24,37.762) 17.149,39.671 ccw(c15.24,37.762) P1.27@15.24,40.462 ; P1.27@15.24,40.843 cw(c15.24,39.063) 16.499,40.321 ccw(c15.24,39.063) P1.27@15.24,40.843 ; P1.27@15.355,40.504 cw(c15.834,39.939) 16.357,40.463 ccw(c15.834,39.939) P1.27@15.355,40.504 ; P1.27@15.602,40.213 cw(c16.102,39.623) 16.65,40.17 ccw(c16.102,39.623) P1.27@15.602,40.213 ; 2.4'/2.8'LCD.25@33.81,6.49 ccw(c33.825,7.521) 34.554,6.792 cw(c33.825,7.521) 2.4'/2.8'LCD.25@33.81,6.49 ; 2.4'/2.8'LCD.25@34.404,6.274 cw(c35.293,6.274) 34.665,6.903 ccw(c35.293,6.274) 2.4'/2.8'LCD.25@34.404,6.274 ; P2.49@69.708,12.304 cw(c68.933,11.529) 70.029,11.529 ccw(c68.933,11.529) P2.49@69.708,12.304 ; 70.029,11.169 cw(c71.635,11.169) 70.5,12.304 ccw(c71.635,11.169) 70.029,11.169
  Top Layer w0.508: v1(6.934,73.457) 11.074,73.457 11.684,74.066 R1.1@11.684,75.186 ; JTAG.2@14.3,96.596 16.942,99.238 53.926,99.238 R13.2@55.374,97.79 R17.2@58.422,97.79 R19.2@64.518,97.79 66.169,99.441 68.961,99.441 R20.1@70.612,97.79 R21.1@73.66,97.79 ; C39.1@35.56,73.662 35.56,70.383 35.839,70.104 U7.8@37.196,70.104 38.964,70.104 39.218,69.85 R38.2@40.642,69.85 R37.2@43.69,69.85 44.45,69.85 ; v1(39.395,88.798) Y4.4@41.486,88.798 ; Y4.4@41.656,88.968 v1(41.656,92.075) ; C14.2@47.446,54.889 48.87,54.889 49.555,55.575 49.555,59.461 48.92,60.096 v1(47.727,60.096) ; R22.1@65,69.088 64.975,69.063 59.919,69.063 R14.1@54.305,69.063 54.305,67.767 50.8,64.262 v1(47.727,64.262) 46.279,64.262 44.78,65.761 44.78,69.52 44.45,69.85 ; U6.7@83.541,67.31 U6.8@83.541,68.58 C38.1@86.638,68.58 v1@86.638,72.084 ; v1(86.639,72.085) v1@86.638,72.084 ; C11.1@93.47,53.34 v1(95.326,53.34) ; v1(95.326,70.612) 95.326,71.247 94.49,72.084 v1@86.638,72.084 ; 11.684,74.266 cw(c12.604,74.266) 11.953,74.916 ccw(c12.604,74.266) 11.684,74.266 ; 11.684,74.266 ccw(c10.764,74.266) 11.415,74.916 cw(c10.764,74.266) 11.684,74.266 ; 35.56,72.742 cw(c36.48,72.742) 35.829,73.392 ccw(c36.48,72.742) 35.56,72.742 ; 35.56,72.742 ccw(c34.64,72.742) 35.291,73.392 cw(c34.64,72.742) 35.56,72.742 ; 39.722,69.85 cw(c39.722,68.93) 40.372,69.581 ccw(c39.722,68.93) 39.722,69.85 ; 39.722,69.85 ccw(c39.722,70.77) 40.372,70.119 cw(c39.722,70.77) 39.722,69.85 ; 41.561,69.85 cw(c41.561,70.77) 40.911,70.119 ccw(c41.561,70.77) 41.561,69.85 ; 41.561,69.85 ccw(c41.561,68.93) 40.911,69.581 cw(c41.561,68.93) 41.561,69.85 ; 41.656,91.16 cw(c39.614,91.16) 41.058,89.716 ccw(c39.614,91.16) 41.656,91.16 ; 41.656,91.16 ccw(c43.698,91.16) 42.254,89.716 cw(c43.698,91.16) 41.656,91.16 ; 42.77,69.85 cw(c42.77,68.93) 43.42,69.581 ccw(c42.77,68.93) 42.77,69.85 ; 42.77,69.85 ccw(c42.77,70.77) 43.42,70.119 cw(c42.77,70.77) 42.77,69.85 ; 44.45,69.85 cw(c44.45,70.418) 43.995,70.078 ccw(c44.45,70.418) 44.45,69.85 ; 44.45,69.85 ccw(c44.45,69.282) 43.995,69.622 cw(c44.45,69.282) 44.45,69.85 ; 48.365,54.889 cw(c48.365,55.809) 47.715,55.159 ccw(c48.365,55.809) 48.365,54.889 ; 48.365,54.889 ccw(c48.365,53.97) 47.715,54.62 cw(c48.365,53.97) 48.365,54.889 ; 54.305,68.016 cw(c55.225,68.016) 54.575,68.666 ccw(c55.225,68.016) 54.305,68.016 ; 54.305,68.016 ccw(c53.385,68.016) 54.036,68.666 cw(c53.385,68.016) 54.305,68.016 ; 55.225,69.063 cw(c55.225,69.982) 54.575,69.332 ccw(c55.225,69.982) 55.225,69.063 ; 55.225,69.063 ccw(c55.225,68.143) 54.575,68.793 cw(c55.225,68.143) 55.225,69.063 ; 56.293,97.79 cw(c56.293,98.71) 55.643,98.059 ccw(c56.293,98.71) 56.293,97.79 ; 56.293,97.79 ccw(c56.293,96.87) 55.643,97.521 cw(c56.293,96.87) 56.293,97.79 ; 57.502,97.79 cw(c57.502,96.87) 58.152,97.521 ccw(c57.502,96.87) 57.502,97.79 ; 57.502,97.79 ccw(c57.502,98.71) 58.152,98.059 cw(c57.502,98.71) 57.502,97.79 ; 59.341,97.79 cw(c59.341,98.71) 58.691,98.059 ccw(c59.341,98.71) 59.341,97.79 ; 59.341,97.79 ccw(c59.341,96.87) 58.691,97.521 cw(c59.341,96.87) 59.341,97.79 ; 60.55,97.79 cw(c60.55,96.87) 61.2,97.521 ccw(c60.55,96.87) 60.55,97.79 ; 60.55,97.79 ccw(c60.55,98.71) 61.2,98.059 cw(c60.55,98.71) 60.55,97.79 ; 62.389,97.79 cw(c62.389,98.71) 61.739,98.059 ccw(c62.389,98.71) 62.389,97.79 ; 62.389,97.79 ccw(c62.389,96.87) 61.739,97.521 cw(c62.389,96.87) 62.389,97.79 ; 63.598,97.79 cw(c63.598,96.87) 64.248,97.521 ccw(c63.598,96.87) 63.598,97.79 ; 63.598,97.79 ccw(c63.598,98.71) 64.248,98.059 cw(c63.598,98.71) 63.598,97.79 ; 71.532,97.79 cw(c71.532,98.71) 70.881,98.059 ccw(c71.532,98.71) 71.532,97.79 ; 71.532,97.79 ccw(c71.532,96.87) 70.881,97.521 cw(c71.532,96.87) 71.532,97.79 ; 72.74,97.79 cw(c72.74,96.87) 73.391,97.521 ccw(c72.74,96.87) 72.74,97.79 ; 72.74,97.79 ccw(c72.74,98.71) 73.391,98.059 cw(c72.74,98.71) 72.74,97.79 ; 85.718,68.58 cw(c85.718,67.66) 86.368,68.311 ccw(c85.718,67.66) 85.718,68.58 ; 85.718,68.58 ccw(c85.718,69.5) 86.368,68.849 cw(c85.718,69.5) 85.718,68.58 ; 86.638,69.627 cw(c85.718,69.627) 86.368,68.976 ccw(c85.718,69.627) 86.638,69.627 ; 86.638,69.627 ccw(c87.558,69.627) 86.907,68.976 cw(c87.558,69.627) 86.638,69.627 ; 94.39,53.34 cw(c94.39,54.26) 93.74,53.609 ccw(c94.39,54.26) 94.39,53.34 ; 94.39,53.34 ccw(c94.39,52.42) 93.74,53.071 cw(c94.39,52.42) 94.39,53.34 ; JTAG.2@14.3,97.13 ccw(c14.3,98.417) 15.211,97.507 cw(c14.3,98.417) JTAG.2@14.3,97.13 ; JTAG.2@14.796,96.634 cw(c15.903,96.634) 15.12,97.416 ccw(c15.903,96.634) JTAG.2@14.796,96.634 ; v1@39.566,88.798 ccw(c39.566,90.908) 41.058,89.416 cw(c39.566,90.908) v1@39.566,88.798 ; 39.661,88.798 cw(c39.661,86.823) 41.058,88.22 ccw(c39.661,86.823) 39.661,88.798 ; R37.2@43.606,69.818 cw(c44.043,69.321) 44.511,69.789 ccw(c44.043,69.321) R37.2@43.606,69.818 ; R37.2@43.643,69.841 cw(c43.994,68.945) 44.675,69.625 ccw(c43.994,68.945) R37.2@43.643,69.841 ; R37.2@43.941,69.437 cw(c44.401,68.914) 44.894,69.406 ccw(c44.401,68.914) R37.2@43.941,69.437 ; 54.506,98.657 ccw(c55.374,99.524) 55.374,98.298 cw(c55.374,99.524) 54.506,98.657 ; R13.2@54.813,98.351 cw(c54.379,97.917) 54.993,97.917 ccw(c54.379,97.917) R13.2@54.813,98.351 ; 56.336,69.063 ccw(c56.336,70.156) 57.109,69.383 cw(c56.336,70.156) 56.336,69.063 ; 56.581,69.063 cw(c56.581,68.316) 57.109,68.844 ccw(c56.581,68.316) 56.581,69.063 ; R25.1@57.648,68.844 cw(c58.176,68.316) 58.176,69.063 ccw(c58.176,68.316) R25.1@57.648,68.844 ; R25.1@57.648,69.383 ccw(c58.421,70.156) 58.421,69.063 cw(c58.421,70.156) R25.1@57.648,69.383 ; 58.876,69.063 ccw(c58.876,70.156) 59.649,69.383 cw(c58.876,70.156) 58.876,69.063 ; 59.121,69.063 cw(c59.121,68.316) 59.649,68.844 ccw(c59.121,68.316) 59.121,69.063 ; R24.1@60.188,68.844 cw(c60.716,68.316) 60.716,69.063 ccw(c60.716,68.316) R24.1@60.188,68.844 ; R24.1@60.188,69.383 ccw(c60.961,70.156) 60.961,69.063 cw(c60.961,70.156) R24.1@60.188,69.383 ; 61.479,69.063 ccw(c61.479,70.069) 62.191,69.357 cw(c61.479,70.069) 61.479,69.063 ; 61.602,69.063 cw(c61.602,68.23) 62.191,68.819 ccw(c61.602,68.23) 61.602,69.063 ; R23.1@62.73,68.819 cw(c63.319,68.23) 63.319,69.063 ccw(c63.319,68.23) R23.1@62.73,68.819 ; R23.1@62.73,69.357 ccw(c63.441,70.069) 63.441,69.063 cw(c63.441,70.069) R23.1@62.73,69.357 ; 64.019,69.063 ccw(c64.019,70.069) 64.731,69.357 cw(c64.019,70.069) 64.019,69.063 ; 64.142,69.063 cw(c64.142,68.23) 64.731,68.819 ccw(c64.142,68.23) 64.142,69.063 ; R19.2@64.518,98.298 ccw(c64.518,99.524) 65.385,98.657 cw(c64.518,99.524) R19.2@64.518,98.298 ; R19.2@64.899,97.917 cw(c65.512,97.917) 65.078,98.351 ccw(c65.512,97.917) R19.2@64.899,97.917 ; 69.745,98.657 ccw(c70.612,99.524) 70.612,98.298 cw(c70.612,99.524) 69.745,98.657 ; R20.1@70.051,98.351 cw(c69.618,97.917) 70.231,97.917 ccw(c69.618,97.917) R20.1@70.051,98.351
  Top Layer w1.016: C13.2@44.677,54.889 C14.2@47.446,54.889 ; U8.4@76.454,53.596 R6.2@76.454,58.93 ; U8.4@76.71,53.341 U8.2@82.806,53.341 C10.1@87.884,53.34 ; C10.1@87.884,53.34 C11.1@93.47,53.34 ; U8.4@77.248,53.88 ccw(c78.549,55.18) 78.549,53.341 ; U8.4@77.248,53.88 cw(c79.166,55.797) 76.454,55.797 ccw(c79.166,55.797) U8.4@77.248,53.88 ; U8.4@77.248,53.88 ccw(c78.549,55.18) 78.549,53.341 ; 78.549,53.341 ccw(c78.549,51.501) 77.248,52.802 cw(c78.549,51.501) 78.549,53.341
  Bottom Layer w0.254: v1(36.017,45.087) C16.2@36.235,45.306 ; v1(42.088,45.11) 42.116,45.11 43.282,43.945 v1(43.282,41.046) 43.282,29.234 C18.2@44.501,28.015 ; v1(56.794,92.405) v1(56.794,97.815) ; 43.282,37.87 cw(c43.588,37.87) 43.371,38.086 ccw(c43.588,37.87) 43.282,37.87 ; 43.282,37.87 ccw(c42.975,37.87) 43.192,38.086 cw(c42.975,37.87) 43.282,37.87 ; 43.282,38.483 cw(c42.975,38.483) 43.192,38.266 ccw(c42.975,38.483) 43.282,38.483 ; 43.282,38.483 ccw(c43.588,38.483) 43.371,38.266 cw(c43.588,38.483) 43.282,38.483 ; 43.282,40.74 cw(c43.588,40.74) 43.371,40.957 ccw(c43.588,40.74) 43.282,40.74 ; 43.282,40.74 ccw(c42.975,40.74) 43.192,40.957 cw(c42.975,40.74) 43.282,40.74 ; 43.282,41.353 cw(c42.975,41.353) 43.192,41.136 ccw(c42.975,41.353) 43.282,41.353 ; 43.282,41.353 ccw(c43.588,41.353) 43.371,41.136 cw(c43.588,41.353) 43.282,41.353 ; 56.794,92.712 cw(c56.488,92.712) 56.705,92.495 ccw(c56.488,92.712) 56.794,92.712 ; 56.794,92.712 ccw(c57.101,92.712) 56.884,92.495 cw(c57.101,92.712) 56.794,92.712 ; 56.794,97.509 cw(c57.101,97.509) 56.884,97.726 ccw(c57.101,97.509) 56.794,97.509 ; 56.794,97.509 ccw(c56.488,97.509) 56.705,97.726 cw(c56.488,97.509) 56.794,97.509 ; v1@42.088,44.983 cw(c42.088,44.609) 42.353,44.874 ccw(c42.088,44.609) v1@42.088,44.983 ; v1@42.215,45.11 ccw(c42.453,45.11) 42.285,44.942 cw(c42.453,45.11) v1@42.215,45.11 ; 43.417,29.099 cw(c42.333,28.015) 43.866,28.015 ccw(c42.333,28.015) 43.417,29.099 ; 43.723,28.792 ccw(c44.374,29.442) 44.374,28.523 cw(c44.374,29.442) 43.723,28.792 ; 43.85,28.665 cw(c43.2,28.015) 44.12,28.015 ccw(c43.2,28.015) 43.85,28.665 ; C18.2@44.267,28.248 cw(c44.01,27.991) 44.374,27.991 ccw(c44.01,27.991) C18.2@44.267,28.248 ; C18.2@44.325,28.191 ccw(c44.501,28.367) 44.501,28.118 cw(c44.501,28.367) C18.2@44.325,28.191
  Bottom Layer w0.381: v1(24.486,39.268) 30.988,39.268 31.394,38.862 v1(31.394,37.414) C12.1@31.394,37.413 31.572,37.235 31.572,22.784 v1(35.433,18.923) 33.782,17.272 C31.2@33.782,8.968 33.782,6.299 2.4'/2.8'LCD.25@33.807,6.274 2.4'/2.8'LCD.24@36.347,3.734 ; v1(73.965,72.314) 74.805,71.474 v1(74.805,66.038) ; 31.394,38.486 cw(c30.321,38.486) 31.08,37.727 ccw(c30.321,38.486) 31.394,38.486 ; 31.394,38.486 ccw(c32.468,38.486) 31.709,37.727 cw(c32.468,38.486) 31.394,38.486 ; 33.782,7.895 cw(c34.855,7.895) 34.096,8.654 ccw(c34.855,7.895) 33.782,7.895 ; 33.782,7.895 ccw(c32.709,7.895) 33.468,8.654 cw(c32.709,7.895) 33.782,7.895 ; 33.782,10.041 cw(c32.709,10.041) 33.468,9.282 ccw(c32.709,10.041) 33.782,10.041 ; 33.782,10.041 ccw(c34.855,10.041) 34.096,9.282 cw(c34.855,10.041) 33.782,10.041 ; 34.826,5.255 cw(c35.845,6.274) 34.404,6.274 ccw(c35.845,6.274) 34.826,5.255 ; 34.826,5.255 ccw(c33.807,4.236) 33.807,5.677 cw(c33.807,4.236) 34.826,5.255 ; 35.328,4.753 cw(c34.309,3.734) 35.75,3.734 ccw(c34.309,3.734) 35.328,4.753 ; 35.328,4.753 ccw(c36.347,5.772) 36.347,4.331 cw(c36.347,5.772) 35.328,4.753 ; C12.1@31.207,37.098 cw(c30.326,36.217) 31.572,36.217 ccw(c30.326,36.217) C12.1@31.207,37.098 ; C12.1@31.349,37.369 cw(c30.812,36.832) 31.572,36.832 ccw(c30.812,36.832) C12.1@31.349,37.369 ; 31.572,36.462 cw(c32.472,36.462) 31.836,37.098 ccw(c32.472,36.462) 31.572,36.462 ; 2.4'/2.8'LCD.25@33.385,6.696 ccw(c32.428,7.654) 33.782,7.654 cw(c32.428,7.654) 2.4'/2.8'LCD.25@33.385,6.696 ; 33.782,7.776 ccw(c35.31,7.776) 34.229,6.696 cw(c35.31,7.776) 33.782,7.776
  Bottom Layer w0.508: v1(6.934,73.457) 6.934,77.14 5.41,78.664 BOOT.1@5.41,82.931 BOOT.2@5.41,85.471 5.41,89.281 9.525,93.396 9.525,95.326 10.795,96.596 JTAG.2@14.3,96.596 JTAG.1@14.3,94.056 ; JTAG.1@14.287,94.043 16.864,91.467 R2.1@19.634,91.467 ; P1.29@15.24,38.1 P1.27@15.24,40.64 P1.25@15.24,43.18 P1.23@15.24,45.72 ; C29.2@36.347,1.5 2.4'/2.8'LCD.24@36.347,3.734 ; L1.1@38.43,84.834 38.43,87.833 v1(39.395,88.798) ; v1(41.656,92.075) v1@41.656,99.238 ; v1(47.727,60.096) v1(47.727,64.262) ; v1(56.921,84.557) C25.1@57.148,84.557 C26.1@60.022,84.557 ; J1.4@79.781,81.25 86.289,81.25 87.171,80.367 ; J1.5@82.321,82.52 83.217,83.415 C27.1@89.687,83.415 C28.1@89.687,80.367 ; v1(86.639,72.085) 86.639,73.077 87.046,73.483 87.046,74.684 86.546,75.183 86.546,79.742 87.171,80.367 ; R30.1@92.456,25.906 R29.1@92.456,28.446 R28.1@92.456,31.494 R27.1@92.456,34.034 R26.1@92.456,36.574 92.456,49.047 95.326,51.918 v1(95.326,53.34) v1(95.326,70.612) ; R39.1@96.01,86.208 R40.2@96.01,77.597 95.02,76.606 91.415,76.606 89.687,78.334 C28.1@89.687,80.367 ; 5.41,81.734 cw(c6.608,81.734) 5.761,82.58 ccw(c6.608,81.734) 5.41,81.734 ; 5.41,81.734 ccw(c4.213,81.734) 5.059,82.58 cw(c4.213,81.734) 5.41,81.734 ; 5.41,84.128 cw(c4.213,84.128) 5.059,83.282 ccw(c4.213,84.128) 5.41,84.128 ; 5.41,84.128 ccw(c6.608,84.128) 5.761,83.282 cw(c6.608,84.128) 5.41,84.128 ; 5.41,84.274 cw(c6.608,84.274) 5.761,85.12 ccw(c6.608,84.274) 5.41,84.274 ; 5.41,84.274 ccw(c4.213,84.274) 5.059,85.12 cw(c4.213,84.274) 5.41,84.274 ; 5.41,86.668 cw(c4.213,86.668) 5.059,85.822 ccw(c4.213,86.668) 5.41,86.668 ; 5.41,86.668 ccw(c6.608,86.668) 5.761,85.822 cw(c6.608,86.668) 5.41,86.668 ; 13.103,96.596 cw(c13.103,95.399) 13.949,96.245 ccw(c13.103,95.399) 13.103,96.596 ; 13.103,96.596 ccw(c13.103,97.794) 13.949,96.947 cw(c13.103,97.794) 13.103,96.596 ; 14.3,95.291 cw(c13.103,95.291) 13.949,94.444 ccw(c13.103,95.291) 14.3,95.291 ; 14.3,95.291 ccw(c15.498,95.291) 14.651,94.444 cw(c15.498,95.291) 14.3,95.291 ; 14.3,95.361 cw(c15.498,95.361) 14.651,96.208 ccw(c15.498,95.361) 14.3,95.361 ; 14.3,95.361 ccw(c13.103,95.361) 13.949,96.208 cw(c13.103,95.361) 14.3,95.361 ; 15.24,39.297 cw(c14.043,39.297) 14.889,38.451 ccw(c14.043,39.297) 15.24,39.297 ; 15.24,39.297 ccw(c16.437,39.297) 15.591,38.451 cw(c16.437,39.297) 15.24,39.297 ; 15.24,39.443 cw(c16.437,39.443) 15.591,40.289 ccw(c16.437,39.443) 15.24,39.443 ; 15.24,39.443 ccw(c14.043,39.443) 14.889,40.289 cw(c14.043,39.443) 15.24,39.443 ; 15.24,41.837 cw(c14.043,41.837) 14.889,40.991 ccw(c14.043,41.837) 15.24,41.837 ; 15.24,41.837 ccw(c16.437,41.837) 15.591,40.991 cw(c16.437,41.837) 15.24,41.837 ; 15.24,41.983 cw(c16.437,41.983) 15.591,42.829 ccw(c16.437,41.983) 15.24,41.983 ; 15.24,41.983 ccw(c14.043,41.983) 14.889,42.829 cw(c14.043,41.983) 15.24,41.983 ; 15.24,44.377 cw(c14.043,44.377) 14.889,43.531 ccw(c14.043,44.377) 15.24,44.377 ; 15.24,44.377 ccw(c16.437,44.377) 15.591,43.531 cw(c16.437,44.377) 15.24,44.377 ; 15.24,44.523 cw(c16.437,44.523) 15.591,45.369 ccw(c16.437,44.523) 15.24,44.523 ; 15.24,44.523 ccw(c14.043,44.523) 14.889,45.369 cw(c14.043,44.523) 15.24,44.523 ; 18.587,91.467 cw(c18.587,90.547) 19.238,91.198 ccw(c18.587,90.547) 18.587,91.467 ; 18.587,91.467 ccw(c18.587,92.387) 19.238,91.736 cw(c18.587,92.387) 18.587,91.467 ; 36.347,2.446 cw(c37.635,2.446) 36.725,3.357 ccw(c37.635,2.446) 36.347,2.446 ; 36.347,2.446 ccw(c35.06,2.446) 35.97,3.357 cw(c35.06,2.446) 36.347,2.446 ; 38.43,85.754 cw(c37.51,85.754) 38.161,85.104 ccw(c37.51,85.754) 38.43,85.754 ; 38.43,85.754 ccw(c39.35,85.754) 38.7,85.104 cw(c39.35,85.754) 38.43,85.754 ; 58.068,84.557 cw(c58.068,85.476) 57.418,84.826 ccw(c58.068,85.476) 58.068,84.557 ; 58.068,84.557 ccw(c58.068,83.637) 57.418,84.287 cw(c58.068,83.637) 58.068,84.557 ; 81.008,81.25 cw(c81.008,82.476) 80.141,81.609 ccw(c81.008,82.476) 81.008,81.25 ; 81.008,81.25 ccw(c81.008,80.023) 80.141,80.89 cw(c81.008,80.023) 81.008,81.25 ; 83.189,83.387 cw(c82.321,84.254) 82.321,83.028 ccw(c82.321,84.254) 83.189,83.387 ; 83.189,83.387 ccw(c84.056,82.52) 82.829,82.52 cw(c84.056,82.52) 83.189,83.387 ; 87.171,80.367 C28.1@89.687,80.367 ; 88.641,80.367 cw(c88.641,79.447) 89.291,80.098 ccw(c88.641,79.447) 88.641,80.367 ; 88.641,80.367 ccw(c88.641,81.287) 89.291,80.637 cw(c88.641,81.287) 88.641,80.367 ; 88.641,83.415 cw(c88.641,82.495) 89.291,83.146 ccw(c88.641,82.495) 88.641,83.415 ; 88.641,83.415 ccw(c88.641,84.335) 89.291,83.685 cw(c88.641,84.335) 88.641,83.415 ; 89.687,79.447 cw(c90.607,79.447) 89.957,80.098 ccw(c90.607,79.447) 89.687,79.447 ; 89.687,79.447 ccw(c88.768,79.447) 89.418,80.098 cw(c88.768,79.447) 89.687,79.447 ; 89.687,81.287 cw(c88.768,81.287) 89.418,80.637 ccw(c88.768,81.287) 89.687,81.287 ; 89.687,81.287 ccw(c90.607,81.287) 89.957,80.637 cw(c90.607,81.287) 89.687,81.287 ; 89.687,82.495 cw(c90.607,82.495) 89.957,83.146 ccw(c90.607,82.495) 89.687,82.495 ; 89.687,82.495 ccw(c88.768,82.495) 89.418,83.146 cw(c88.768,82.495) 89.687,82.495 ; 92.456,26.826 cw(c91.536,26.826) 92.187,26.176 ccw(c91.536,26.826) 92.456,26.826 ; 92.456,26.826 ccw(c93.376,26.826) 92.725,26.176 cw(c93.376,26.826) 92.456,26.826 ; 92.456,27.527 cw(c93.376,27.527) 92.725,28.177 ccw(c93.376,27.527) 92.456,27.527 ; 92.456,27.527 ccw(c91.536,27.527) 92.187,28.177 cw(c91.536,27.527) 92.456,27.527 ; 92.456,29.366 cw(c91.536,29.366) 92.187,28.716 ccw(c91.536,29.366) 92.456,29.366 ; 92.456,29.366 ccw(c93.376,29.366) 92.725,28.716 cw(c93.376,29.366) 92.456,29.366 ; 92.456,30.575 cw(c93.376,30.575) 92.725,31.225 ccw(c93.376,30.575) 92.456,30.575 ; 92.456,30.575 ccw(c91.536,30.575) 92.187,31.225 cw(c91.536,30.575) 92.456,30.575 ; 92.456,32.414 cw(c91.536,32.414) 92.187,31.764 ccw(c91.536,32.414) 92.456,32.414 ; 92.456,32.414 ccw(c93.376,32.414) 92.725,31.764 cw(c93.376,32.414) 92.456,32.414 ; 92.456,33.115 cw(c93.376,33.115) 92.725,33.765 ccw(c93.376,33.115) 92.456,33.115 ; 92.456,33.115 ccw(c91.536,33.115) 92.187,33.765 cw(c91.536,33.115) 92.456,33.115 ; 92.456,34.954 cw(c91.536,34.954) 92.187,34.304 ccw(c91.536,34.954) 92.456,34.954 ; 92.456,34.954 ccw(c93.376,34.954) 92.725,34.304 cw(c93.376,34.954) 92.456,34.954 ; 92.456,35.655 cw(c93.376,35.655) 92.725,36.305 ccw(c93.376,35.655) 92.456,35.655 ; 92.456,35.655 ccw(c91.536,35.655) 92.187,36.305 cw(c91.536,35.655) 92.456,35.655 ; 92.456,37.494 cw(c91.536,37.494) 92.187,36.844 ccw(c91.536,37.494) 92.456,37.494 ; 92.456,37.494 ccw(c93.376,37.494) 92.725,36.844 cw(c93.376,37.494) 92.456,37.494 ; 96.01,78.644 cw(c95.091,78.644) 95.741,77.993 ccw(c95.091,78.644) 96.01,78.644 ; 96.01,78.644 ccw(c96.93,78.644) 96.28,77.993 cw(c96.93,78.644) 96.01,78.644 ; 96.01,85.161 cw(c96.93,85.161) 96.28,85.811 ccw(c96.93,85.161) 96.01,85.161 ; 96.01,85.161 ccw(c95.091,85.161) 95.741,85.811 cw(c95.091,85.161) 96.01,85.161 ; JTAG.1@14.3,93.523 cw(c14.3,92.296) 15.167,93.164 ccw(c14.3,92.296) JTAG.1@14.3,93.523 ; JTAG.1@14.796,94.019 ccw(c15.965,94.019) 15.138,93.193 cw(c15.965,94.019) JTAG.1@14.796,94.019 ; C29.2@36.027,1.719 ccw(c35.254,2.492) 36.347,2.492 cw(c35.254,2.492) C29.2@36.027,1.719 ; 36.347,2.247 ccw(c37.094,2.247) 36.566,1.719 cw(c37.094,2.247) 36.347,2.247 ; 58.941,84.557 cw(c58.941,83.556) 59.649,84.263 ccw(c58.941,83.556) 58.941,84.557 ; 59.056,84.557 ccw(c59.056,85.395) 59.649,84.802 cw(c59.056,85.395) 59.056,84.557 ; 95.143,76.73 cw(c96.01,75.863) 96.01,77.089 ccw(c96.01,75.863) 95.143,76.73 ; R40.2@95.45,77.036 ccw(c95.016,77.47) 95.629,77.47 cw(c95.016,77.47) R40.2@95.45,77.036
  other v1: 41.681,99.238
50MHZ: R15.1 U2.34 Y4.3 | length 37.9
  Top Layer w0.254: Y4.3@46.736,88.968 55.583,88.968 56.162,88.389 U2.34@56.162,86.904 ; 47.859,88.968 cw(c47.859,90.091) 47.065,89.297 ccw(c47.859,90.091) 47.859,88.968 ; 47.859,88.968 ccw(c47.859,87.845) 47.065,88.639 cw(c47.859,87.845) 47.859,88.968 ; 48.472,88.968 cw(c48.472,90.704) 47.244,89.476 ccw(c48.472,90.704) 48.472,88.968 ; 48.472,88.968 ccw(c48.472,87.232) 47.244,88.46 cw(c48.472,87.232) 48.472,88.968 ; 49.085,88.968 cw(c49.085,91.317) 47.424,89.656 ccw(c49.085,91.317) 49.085,88.968 ; 49.085,88.968 ccw(c49.085,86.619) 47.424,88.28 cw(c49.085,86.619) 49.085,88.968 ; 51.998,88.968 ccw(c51.998,89.303) 52.234,89.066 cw(c51.998,89.303) 51.998,88.968 ; 52.037,88.968 cw(c52.037,88.689) 52.234,88.886 ccw(c52.037,88.689) 52.037,88.968 ; v1@52.414,88.886 cw(c52.611,88.689) 52.611,88.968 ccw(c52.611,88.689) v1@52.414,88.886 ; v1@52.414,89.066 ccw(c52.65,89.303) 52.65,88.968 cw(c52.65,89.303) v1@52.414,89.066
  Bottom Layer w0.254: v1(52.324,88.976) 52.326,88.978 v1(52.326,95.504) ; 52.326,95.197 cw(c52.632,95.197) 52.415,95.414 ccw(c52.632,95.197) 52.326,95.197 ; 52.326,95.197 ccw(c52.019,95.197) 52.236,95.414 cw(c52.019,95.197) 52.326,95.197 ; v1@52.234,89.066 ccw(c52.013,89.287) 52.326,89.287 cw(c52.013,89.287) v1@52.234,89.066 ; 52.326,89.279 ccw(c52.627,89.279) 52.414,89.066 cw(c52.627,89.279) 52.326,89.279
AGND: C19.2 C34.2 C35.2 C45.2 C46.1 C47.2 C48.2 OPIN.3 R32.2 R43.1 R44.1 U1.20 U11.4 | length 166.2
  Top Layer w0.254: R44.1@1.524,58.469 1.524,53.594 2.288,52.83 ; v1(9.728,54.813) 7.391,54.813 6.833,55.372 U11.4@6.833,55.956 5.105,55.956 3.556,54.407 R43.1@3.556,52.83 2.288,52.83 ; v1(34.544,45.339) 35.979,43.904 36.851,43.904 ; U1.20@37.696,43.156 37.599,43.156 36.851,43.904 ; 1.524,57.243 cw(c2.75,57.243) 1.883,58.11 ccw(c2.75,57.243) 1.524,57.243 ; 1.524,57.243 ccw(c0.298,57.243) 1.165,58.11 cw(c0.298,57.243) 1.524,57.243 ; 2.288,52.83 cw(c2.288,51.802) 3.052,52.49 ccw(c2.288,51.802) 2.288,52.83 ; 2.288,52.83 ccw(c2.288,53.858) 3.052,53.17 cw(c2.288,53.858) 2.288,52.83 ; 3.556,54.057 cw(c2.33,54.057) 3.197,53.19 ccw(c2.33,54.057) 3.556,54.057 ; 3.556,54.057 ccw(c4.782,54.057) 3.915,53.19 cw(c4.782,54.057) 3.556,54.057 ; 5.865,55.956 cw(c5.865,55.496) 6.19,55.821 ccw(c5.865,55.496) 5.865,55.956 ; 5.865,55.956 ccw(c5.865,56.416) 6.19,56.091 cw(c5.865,56.416) 5.865,55.956 ; 6.833,55.496 cw(c7.293,55.496) 6.967,55.821 ccw(c7.293,55.496) 6.833,55.496 ; 6.833,55.496 ccw(c6.373,55.496) 6.698,55.821 cw(c6.373,55.496) 6.833,55.496 ; 9.422,54.813 cw(c9.422,54.507) 9.638,54.723 ccw(c9.422,54.507) 9.422,54.813 ; 9.422,54.813 ccw(c9.422,55.12) 9.638,54.903 cw(c9.422,55.12) 9.422,54.813 ; 34.761,45.122 cw(c34.978,45.339) 34.671,45.339 ccw(c34.978,45.339) 34.761,45.122 ; 34.761,45.122 ccw(c34.544,44.905) 34.544,45.212 cw(c34.544,44.905) 34.761,45.122 ; 36.851,43.904 cw(c36.851,43.641) U1.20@37.078,43.773 ; 36.851,43.904 cw(c36.851,43.641) U1.20@37.078,43.773 ; U1.20@37.078,43.773 cw(c37.078,44.006) 36.914,43.841 ccw(c37.078,44.006) U1.20@37.078,43.773 ; U1.20@37.078,43.773 ccw(c36.762,43.457) 36.762,43.904 cw(c36.762,43.457) U1.20@37.078,43.773 ; 7.038,55.166 ccw(c7.645,55.773) 7.645,54.915 cw(c7.645,55.773) 7.038,55.166 ; v1@7.735,54.698 cw(c8.013,54.42) 8.013,54.813 ccw(c8.013,54.42) v1@7.735,54.698
  Top Layer w0.508: OPIN.3@6.604,44.704 6.77,44.538 v1(25.641,44.538) 25.641,42.533 26.719,41.454 C19.2@28.27,41.454 ; C46.1@6.831,64.999 7.722,64.999 ; v1(7.645,49.276) C45.2@9.396,49.276 ; v1(24.054,69.901) 14.58,69.901 13.157,68.478 v1(13.157,66.065) 13.132,66.04 8.763,66.04 v1(8.509,65.786) ; 7.722,64.999 cw(c7.722,65.849) 7.107,65.262 ccw(c7.722,65.849) 7.722,64.999 ; 7.722,64.999 ccw(c7.722,64.148) 7.107,64.735 cw(c7.722,64.148) 7.722,64.999 ; 7.722,64.999 v1(8.509,65.786) ; v1(8.509,65.786) cw(c9.122,65.173) 9.122,66.04 ccw(c9.122,65.173) v1(8.509,65.786) ; 27.223,41.454 cw(c27.223,40.535) 27.874,41.185 ccw(c27.223,40.535) 27.223,41.454 ; 27.223,41.454 ccw(c27.223,42.374) 27.874,41.724 cw(c27.223,42.374) 27.223,41.454 ; OPIN.3@6.955,44.353 cw(c7.401,43.907) 7.401,44.538 ccw(c7.401,43.907) OPIN.3@6.955,44.353 ; OPIN.3@6.955,45.055 ccw(c8.202,46.302) 8.202,44.538 cw(c8.202,46.302) OPIN.3@6.955,45.055 ; 8.347,49.276 ccw(c8.347,50.201) 9.002,49.547 cw(c8.347,50.201) 8.347,49.276 ; 8.355,49.276 cw(c8.355,48.362) 9.002,49.008 ccw(c8.355,48.362) 8.355,49.276
  Bottom Layer w0.508: OPIN.3@6.604,44.704 7.645,45.745 v1(7.645,49.276) v1(7.645,54.788) ; v1(8.509,65.786) 8.509,58.676 C47.2@9.704,57.48 9.704,54.837 v1(9.728,54.813) ; C48.2@10.897,66.065 v1(13.157,66.065) ; v1(25.641,44.538) 26.441,45.339 v1(34.544,45.339) ; 7.451,45.551 cw(c6.604,46.397) 6.604,45.2 ccw(c6.604,46.397) 7.451,45.551 ; 7.451,45.551 ccw(c8.297,44.704) 7.1,44.704 cw(c8.297,44.704) 7.451,45.551 ; 9.704,56.433 cw(c10.624,56.433) 9.974,57.084 ccw(c10.624,56.433) 9.704,56.433 ; 9.704,56.433 ccw(c8.785,56.433) 9.435,57.084 cw(c8.785,56.433) 9.704,56.433 ; 8.837,58.347 ccw(c9.704,59.215) 9.704,57.988 cw(c9.704,59.215) 8.837,58.347 ; C47.2@9.144,58.041 cw(c8.71,57.607) 9.323,57.607 ccw(c8.71,57.607) C47.2@9.144,58.041 ; C48.2@11.717,65.593 cw(c12.857,64.453) 12.857,66.065 ccw(c12.857,64.453) C48.2@11.717,65.593 ; C48.2@11.717,66.436 ccw(c12.612,67.331) 12.612,66.065 cw(c12.612,67.331) C48.2@11.717,66.436
  Bottom Layer w1.016: v1(24.054,69.901) 24.968,70.815 v1(24.968,78.943) R32.2@24.968,81.786 C34.2@24.968,84.834 C35.2@24.968,87.882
